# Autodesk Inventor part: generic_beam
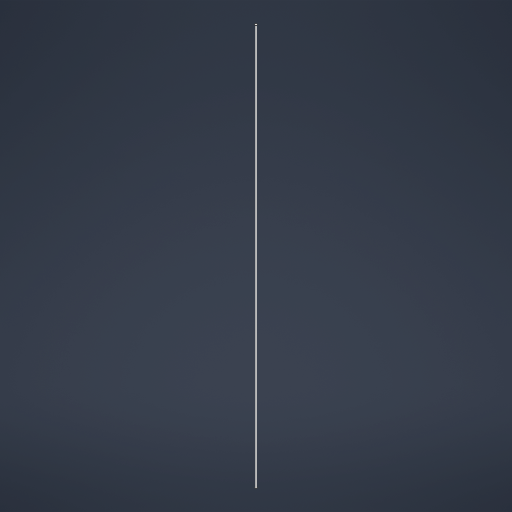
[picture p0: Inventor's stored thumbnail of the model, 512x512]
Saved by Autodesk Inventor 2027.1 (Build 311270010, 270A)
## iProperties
Created: 2026-07
Part Number: generic_beam
Material: Generic
Document SubType Name: Modeling
Designer: dunge
Density: 1 g/cm^3
Appearance: Default
Author: dunge
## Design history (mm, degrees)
sketch "Sketch1"
  geometry: L1 (-9.64, 0.476)-(-10.91, 0.476); L2 (-10.91, 0.476)-(-10.91, -0.794); L3 (-10.91, -0.794)-(-9.64, -0.794); L4 (-9.64, -0.794)-(-9.64, 0.476); C1 r 0.635 at (-10.275, -0.159); 1 further point
  constraints: 8 end point, 2 parallel, 1 centre point, 1 horizontal, 1 perpendicular
  dimensions: "d0" = 1.27 distance of L1.end L2.end; "d1" = 1.27 distance of L2.end L3.end
extrude "Extrusion1" new body sketch "Sketch1" distance "d2" = 254; taper "d3" = 0 deg
body "Solid1"
